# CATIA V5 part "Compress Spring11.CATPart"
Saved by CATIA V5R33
Part number: Compress Spring11
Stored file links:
  C:\Users\Ryzen5700u\Desktop\robot_cicloidale_singolo\Assieme_robot_cicloidale_singolo\Compress Spring11.CATPart

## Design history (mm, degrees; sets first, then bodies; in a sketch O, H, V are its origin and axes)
Body1 "Solid1" (main body)
  Solid1: solid without history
